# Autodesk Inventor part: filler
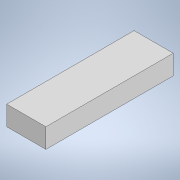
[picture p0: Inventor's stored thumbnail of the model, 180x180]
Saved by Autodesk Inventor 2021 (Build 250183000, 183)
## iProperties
Created: 2026-11
Part Number: filler
Material: Generic
Document SubType Name: Modeling
Designer: hp
Density: 1 g/cm^3
Appearance: Default
Author: hp
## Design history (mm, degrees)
sketch "Sketch1"
  geometry: L1 (0, 0)-(20, 0); L2 (20, 0)-(20, -65); L3 (20, -65)-(0, -65); L4 (0, -65)-(0, 0)
  constraints: 8 end point, 2 parallel, 1 horizontal, 1 perpendicular
  dimensions: "d0" = 20 distance of L2.end L3.end; "d1" = 65 distance of L1.end L2.end
extrude "Extrusion1" new body sketch "Sketch1" distance "d2" = 10; taper "d3" = 0 deg
body "Solid1"
